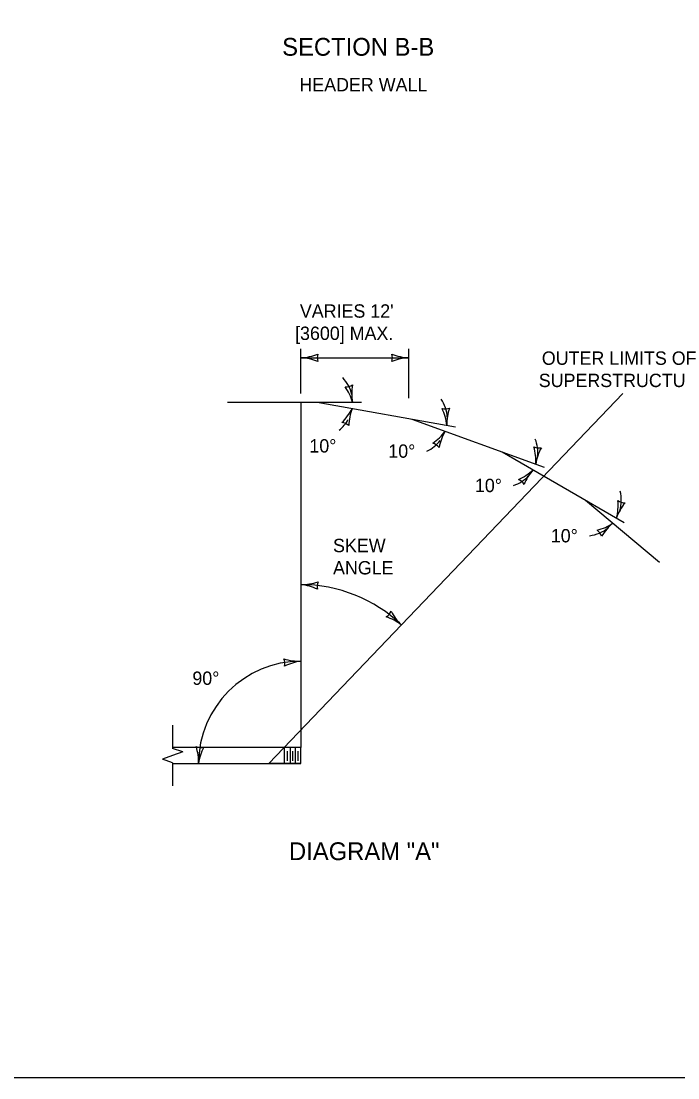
# Model space of a CAD drawing. Extents: x 49991.4 to 50021, y 49987.6 to 50011.4.
# Drawn here: x 50003.539 to 50006.491, y 49987.799 to 49992.545 of the extents above; entities that cross this region are included whole.
import ezdxf

# ---------------------------------------------------------------- set-up
doc = ezdxf.new("R2010")
doc.units = 0
for name, color, linetype in [('Level 1', 7, 'Continuous'), ('Level 2', 7, 'Continuous'), ('Level 3', 7, 'Continuous'), ('Level 4', 7, 'Continuous'), ('Level 5', 7, 'Continuous'), ('Level 6', 7, 'Continuous')]:
    doc.layers.add(name, color=color, linetype=linetype)

msp = doc.modelspace()

# ---------------------------------------------------------------- linework, layer by layer
at = {"layer": 'Level 1'}
for p, q in [((50004.797, 49989.2826), (50004.2203, 49989.2826)), ((50004.7216, 49989.2826), (50004.7216, 49989.2102)), ((50004.7353, 49989.2664), (50004.7353, 49989.2227)), ((50004.7353, 49989.2664), (50004.7353, 49989.2227)), ((50004.7353, 49989.2664), (50004.7353, 49989.2227)), ((50004.7353, 49989.2664), (50004.7353, 49989.2227)), ((50004.7495, 49989.2102), (50004.7495, 49989.2826)), ((50004.759, 49989.2664), (50004.759, 49989.2227)), ((50004.773, 49989.2102), (50004.773, 49989.2826)), ((50004.783, 49989.2664), (50004.783, 49989.2227)), ((50004.797, 49989.2102), (50004.797, 49989.2826)), ((50004.2203, 49989.2102), (50004.797, 49989.2102)), ((50004.797, 49989.2102), (50004.6526, 49989.2102))]:
    msp.add_line(p, q, dxfattribs=at)
msp.add_lwpolyline([(49999.3835, 49998.9992), (50016.7501, 49998.9992), (50016.7501, 49987.7988), (49999.3835, 49987.7988)], close=True, dxfattribs=at)
at = {"layer": 'Level 3'}
for p, q in [((50004.797, 49990.8731), (50004.797, 49991.0732)), ((50005.2812, 49990.8513), (50005.2812, 49991.0732)), ((50004.797, 49991.0332), (50005.2812, 49991.0332)), ((50004.4667, 49990.8331), (50005.0692, 49990.8331)), ((50004.8692, 49990.8331), (50005.4922, 49990.7235)), ((50005.2952, 49990.7581), (50005.8897, 49990.5417)), ((50005.7017, 49990.6101), (50006.2499, 49990.2938)), ((50006.0765, 49990.3935), (50006.408, 49990.1156)), ((50005.7814, 49990.3661), (50005.7814, 49990.3661))]:
    msp.add_line(p, q, dxfattribs=at)
for centre, radius, start, end in [((50004.7855, 49991.2659), 0.233, 272.8273, 292.0772), ((50004.7878, 49990.8111), 0.2223, 67.456, 87.6395), ((50004.9252, 49991.0332), 0.0548, 162.1388, 197.8612), ((50005.2904, 49991.2553), 0.2223, 247.456, 267.6395), ((50005.153, 49991.0332), 0.0548, 342.1388, 17.8612), ((50005.2927, 49990.8005), 0.233, 92.8273, 112.0772), ((50004.8692, 49990.8331), 0.16, 12.6955, 43.8275), ((50004.9998, 49990.9579), 0.0548, 265.4109, 301.1332), ((50005.2475, 49990.8752), 0.2223, 170.7281, 190.9116), ((50004.8053, 49990.7685), 0.233, 16.0994, 35.3492), ((50005.2975, 49990.7573), 0.1576, 3.1968, 35.0307), ((50004.8264, 49990.9016), 0.2223, 314.1674, 334.3509), ((50005.2451, 49990.7239), 0.233, 159.5387, 178.7885), ((50005.4446, 49990.8584), 0.0548, 255.7975, 291.5198), ((50005.2213, 49990.7041), 0.233, 6.486, 25.7358), ((50005.6751, 49990.7355), 0.2223, 161.1147, 181.2982), ((50004.8692, 49990.8331), 0.16, 308.3163, 331.4157), ((50004.9761, 49990.6876), 0.0548, 48.8502, 84.5725), ((50005.2654, 49990.8336), 0.2223, 303.9654, 324.1489), ((50005.646, 49990.5845), 0.233, 149.3367, 168.5865), ((50005.2975, 49990.7573), 0.1576, 294.6786, 322.464), ((50005.3748, 49990.5964), 0.0548, 38.6482, 74.3706), ((50005.8664, 49990.6828), 0.0548, 245.6994, 281.4218), ((50005.6195, 49990.5701), 0.233, 356.3879, 15.6377), ((50005.7049, 49990.609), 0.1566, 353.1502, 21.9681), ((50006.0718, 49990.5214), 0.2223, 151.0166, 171.2001), ((50005.6862, 49990.6905), 0.2223, 293.656, 313.8395), ((50006.0162, 49990.3774), 0.233, 139.0273, 158.2772), ((50005.7049, 49990.609), 0.1566, 287.731, 317.4439), ((50005.7515, 49990.4376), 0.0548, 28.3388, 64.0612), ((50006.0752, 49990.3946), 0.1617, 342.4973, 14.1717), ((50005.9892, 49990.3702), 0.233, 345.9799, 5.2298), ((50006.2524, 49990.4365), 0.0548, 235.2914, 271.0138), ((50006.4252, 49990.2406), 0.2223, 140.6086, 160.7921), ((50006.0752, 49990.3946), 0.1617, 276.5494, 309.581), ((50006.0732, 49990.4739), 0.2223, 284.3102, 304.4937), ((50006.0965, 49990.2138), 0.0548, 18.993, 54.7153), ((50006.3479, 49990.1114), 0.233, 129.6815, 148.9313), ((50004.7986, 49990.2472), 0.233, 269.5959, 288.8458), ((50004.797, 49989.3611), 0.6531, 46.2435, 90.0037), ((50004.7753, 49989.793), 0.2223, 64.2246, 84.4081), ((50004.925, 49990.007), 0.0548, 158.9074, 194.6298), ((50005.1513, 49989.9162), 0.0548, 301.6174, 337.3398), ((50005.1063, 49989.6485), 0.233, 52.3059, 71.5558), ((50005.4, 49989.9958), 0.2223, 206.9346, 227.1181), ((50004.7883, 49989.8926), 0.2223, 252.0677, 272.2512), ((50004.6692, 49989.6601), 0.0548, 346.7505, 22.4729), ((50004.797, 49989.2102), 0.4602, 90, 180), ((50004.8272, 49989.4394), 0.233, 97.439, 116.6889), ((50004.3471, 49989.338), 0.0548, 247.5316, 283.254), ((50004.1039, 49989.2174), 0.233, 358.2201, 17.47), ((50004.5575, 49989.1832), 0.2223, 152.8488, 173.0323)]:
    msp.add_arc(centre, radius, start, end, dxfattribs=at)
at = {"layer": 'Level 4'}
msp.add_line((50004.797, 49990.8331), (50004.797, 49989.2826), dxfattribs=at)
at = {"layer": 'Level 5'}
msp.add_line((50004.6526, 49989.2102), (50006.2442, 49990.8726), dxfattribs=at)
at = {"layer": 'Level 6'}
for p, q in [((50004.2203, 49989.3826), (50004.2203, 49989.2788)), ((50004.266, 49989.2626), (50004.2203, 49989.2788)), ((50004.266, 49989.2626), (50004.2203, 49989.2464)), ((50004.2203, 49989.2464), (50004.1746, 49989.2302)), ((50004.2203, 49989.214), (50004.1746, 49989.2302)), ((50004.2203, 49989.214), (50004.2203, 49989.1102))]:
    msp.add_line(p, q, dxfattribs=at)

# ---------------------------------------------------------------- texts
at = {"layer": 'Level 2'}
for s, height, p in [('SECTION B-B', 0.08, (50004.7126, 49992.3898)), ('HEADER WALL', 0.06, (50004.79, 49992.2298)), ("VARIES 12'", 0.06, (50004.7921, 49991.2132)), ('[3600] MAX.', 0.06, (50004.7706, 49991.1132)), ('OUTER LIMITS OF', 0.06, (50005.8795, 49991.0015)), ('SUPERSTRUCTURE', 0.06, (50005.8658, 49990.9015)), ('10°', 0.06, (50004.8349, 49990.6076)), ('10°', 0.06, (50005.1896, 49990.5841)), ('10°', 0.06, (50005.5789, 49990.4298)), ('10°', 0.06, (50005.9199, 49990.2039)), ('SKEW', 0.06, (50004.9412, 49990.16)), ('ANGLE', 0.06, (50004.9412, 49990.06)), ('90°', 0.06, (50004.309, 49989.5639)), ('DIAGRAM "A"', 0.08, (50004.7432, 49988.7768))]:
    msp.add_text(s, height=height, dxfattribs=at).set_placement(p)

doc.saveas('drawing.dxf')
